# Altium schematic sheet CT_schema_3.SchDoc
size 212 x 173 mm
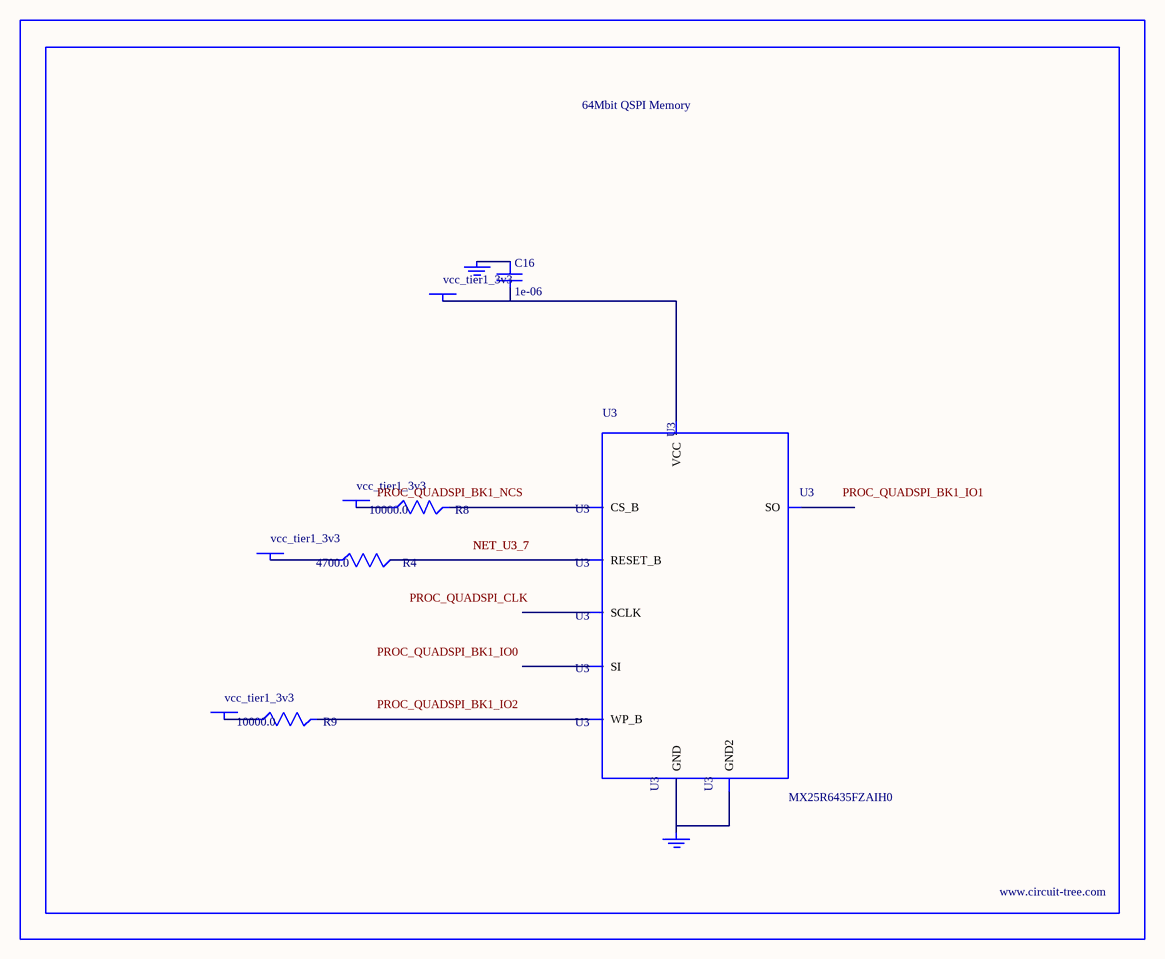
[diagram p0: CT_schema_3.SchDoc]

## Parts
BORDER2  (no value)
C16  1e-06  [C0603]
GND_INSTANCE_2_0  (no value)
GND_INSTANCE_2_1  (no value)
POWER_INSTANCE_2_0  vcc_tier1_3v3
POWER_INSTANCE_2_1  vcc_tier1_3v3
POWER_INSTANCE_2_2  vcc_tier1_3v3
POWER_INSTANCE_2_3  vcc_tier1_3v3
R4  4700.0  [R0603]
R8  10000.0  [R0603]
R9  10000.0  [R0603]
U3  MX25R6435FZAIH0  [WSON-8-PAD]

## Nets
NetC16_1: C16.1 GND_INSTANCE_2_0.0(GND)
NetC16_2: C16.2 POWER_INSTANCE_2_2.0(PWR) U3.8(VCC)
NetGND_INSTANCE_2_1_0: GND_INSTANCE_2_1.0(GND) U3.4(GND) U3.PAD(GND2)
NetPOWER_INSTANCE_2_0_0: POWER_INSTANCE_2_0.0(PWR) R8.1
NetPOWER_INSTANCE_2_1_0: POWER_INSTANCE_2_1.0(PWR) R9.1
NetPOWER_INSTANCE_2_3_0: POWER_INSTANCE_2_3.0(PWR) R4.1
NetR4_2: R4.2 U3.7(RESET_B)
NetR8_2: R8.2 U3.1(CS_B)
NetR9_2: R9.2 U3.3(WP_B)

Not connected (* = marked no-connect by the designer): U3 2(SO) 5(SI) 6(SCLK)

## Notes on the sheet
- Labels drawn without touching a wire or pin: PROC_QUADSPI_BK1_IO0, PROC_QUADSPI_BK1_IO1, PROC_QUADSPI_BK1_IO2, PROC_QUADSPI_BK1_NCS, PROC_QUADSPI_CLK

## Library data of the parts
BORDER2 = BORDER_PAGE2
C16 = C0603C105K3RACTU
GND_INSTANCE_2_0 GND_INSTANCE_2_1 = GND
POWER_INSTANCE_2_0-POWER_INSTANCE_2_3 = PWR
R4 = RC0603JR-074K7L
R8 R9 = RC0603JR-0710KL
